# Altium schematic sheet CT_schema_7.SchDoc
size 254 x 194 mm
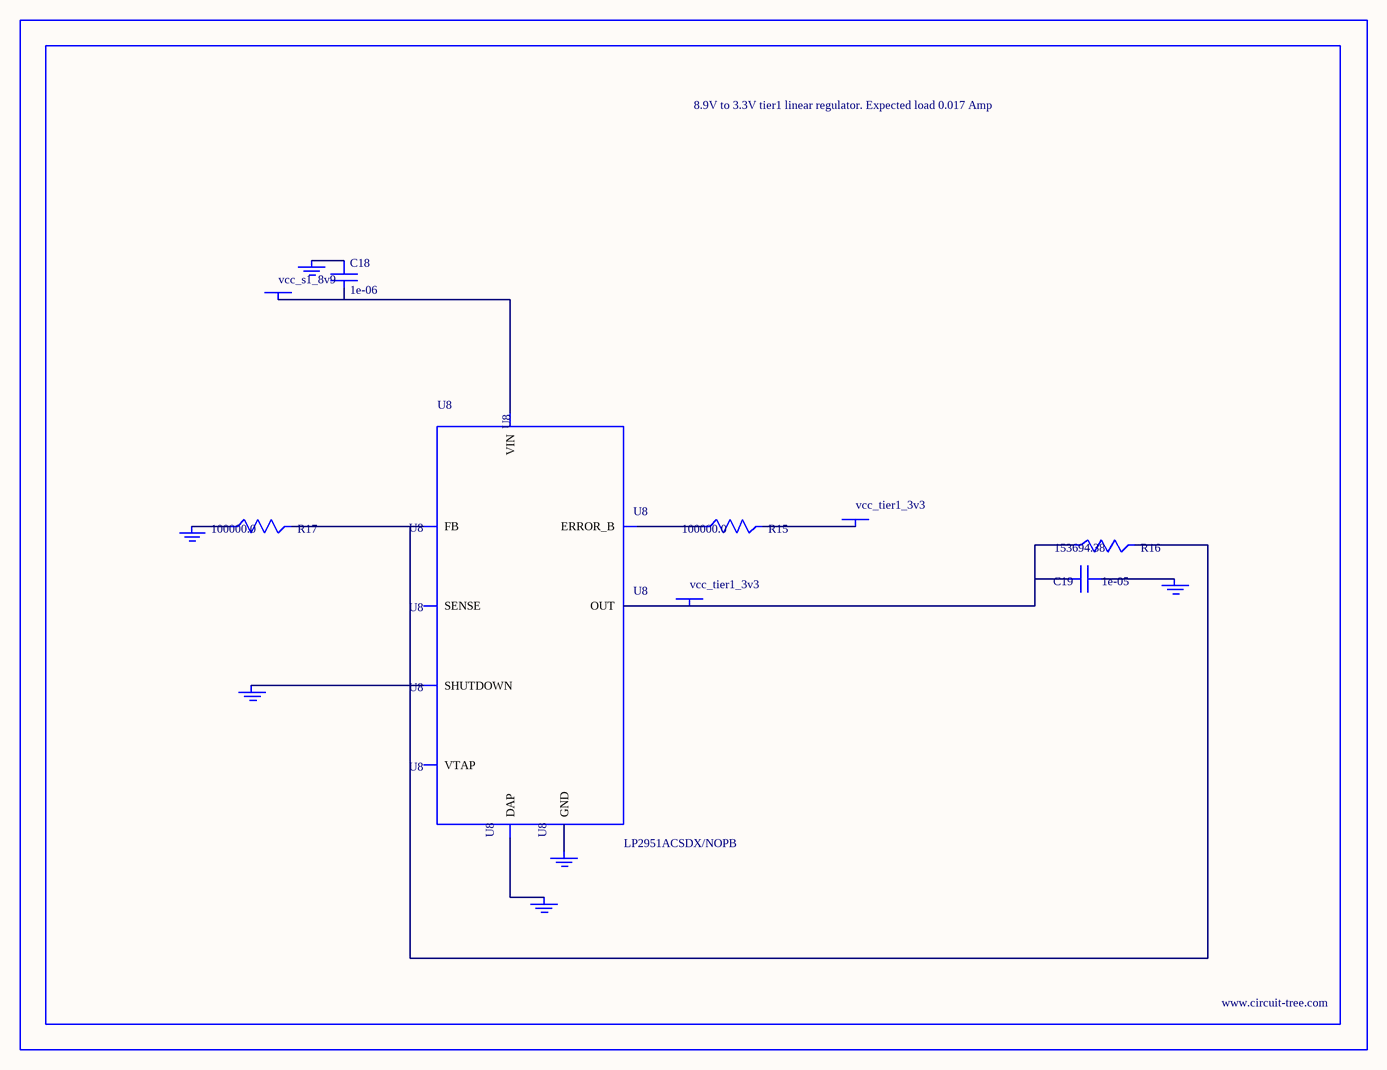
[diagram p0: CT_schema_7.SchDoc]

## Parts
BORDER6  (no value)
C18  1e-06  [C0603]
C19  1e-05  [C1210]
GND_INSTANCE_6_0  (no value)
GND_INSTANCE_6_1  (no value)
GND_INSTANCE_6_2  (no value)
GND_INSTANCE_6_3  (no value)
GND_INSTANCE_6_4  (no value)
GND_INSTANCE_6_5  (no value)
POWER_INSTANCE_6_0  vcc_tier1_3v3
POWER_INSTANCE_6_1  vcc_s1_8v9
POWER_INSTANCE_6_2  vcc_tier1_3v3
R15  100000.0  [R0603]
R16  153694.38  [R0603]
R17  100000.0  [R0603]
U8  LP2951ACSDX/NOPB  [WSON-8]

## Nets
NetC18_1: C18.1 GND_INSTANCE_6_3.0(GND)
NetC18_2: C18.2 POWER_INSTANCE_6_1.0(PWR) U8.8(VIN)
NetC19_1: C19.1 GND_INSTANCE_6_0.0(GND)
NetC19_2: C19.2 POWER_INSTANCE_6_2.0(PWR) R16.1 U8.1(OUT)
NetGND_INSTANCE_6_1_0: GND_INSTANCE_6_1.0(GND) U8.3(SHUTDOWN)
NetGND_INSTANCE_6_2_0: GND_INSTANCE_6_2.0(GND) R17.1
NetGND_INSTANCE_6_4_0: GND_INSTANCE_6_4.0(GND) U8.PAD(DAP)
NetGND_INSTANCE_6_5_0: GND_INSTANCE_6_5.0(GND) U8.4(GND)
NetPOWER_INSTANCE_6_0_0: POWER_INSTANCE_6_0.0(PWR) R15.2
NetR15_1: R15.1 U8.5(ERROR_B)
NetR16_2: R16.2 R17.2 U8.7(FB)

Not connected (* = marked no-connect by the designer): U8 2(SENSE) 6(VTAP)

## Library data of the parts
BORDER6 = BORDER_PAGE6
C18 = C0603C105K3RACTU
C19 = GRM32DR61E106MA12L
GND_INSTANCE_6_0-GND_INSTANCE_6_5 = GND
POWER_INSTANCE_6_0-POWER_INSTANCE_6_2 = PWR
R15 R17 = RC0603JR-07100KL
R16 = R16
